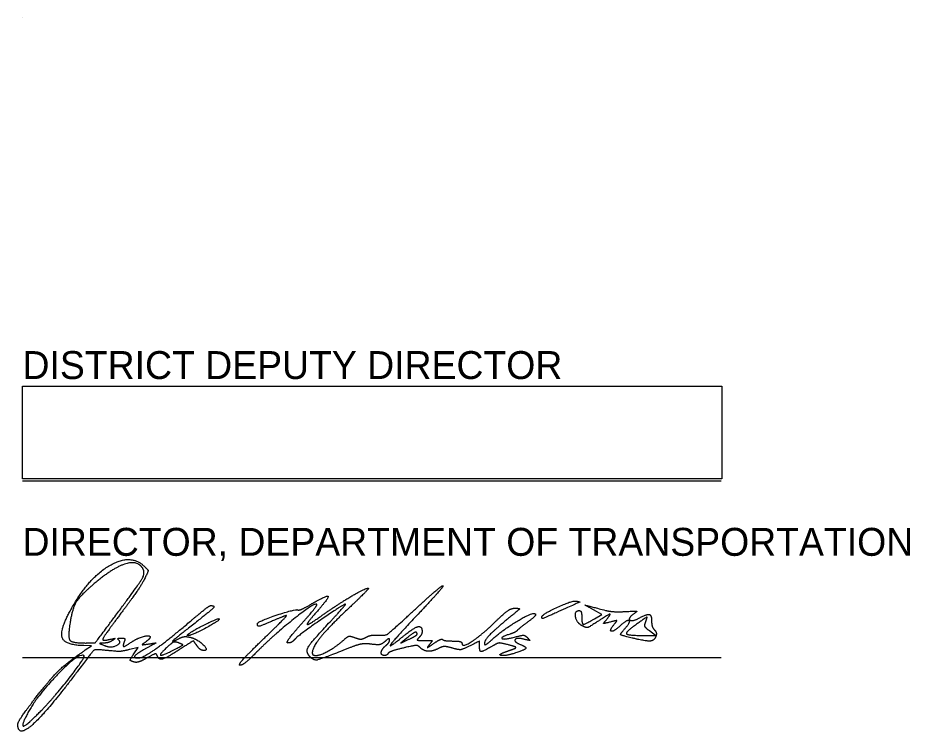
# Model space of a CAD drawing. Extents: x 0 to 91.3, y -0.7 to 22.
# Drawn here: x 24.504 to 28.975, y 7.3 to 10.875 of the extents above; entities that cross this region are included whole.
import ezdxf

# ---------------------------------------------------------------- set-up
doc = ezdxf.new("R2010")
doc.units = 0
doc.layers.add('SH_Data', color=7, linetype='Continuous')
doc.layers.add('SH_Text', color=7, linetype='Continuous')

msp = doc.modelspace()

# ---------------------------------------------------------------- linework, layer by layer
at = {"layer": 'SH_Data'}
for p, q in [((24.5279, 10.875), (24.5279, 10.875)), ((24.5279, 8.555), (28.0279, 8.555)), ((24.5279, 7.6691), (28.0279, 7.6691))]:
    msp.add_line(p, q, dxfattribs=at)
msp.add_lwpolyline([(24.5279, 8.565), (24.5279, 9.0299), (28.032, 9.0299), (28.032, 8.565)], close=True, dxfattribs=at)
at = {"layer": 'SH_Text'}
for p, q in [((24.9902, 7.8741), (24.9902, 7.8741)), ((27.1295, 7.8733), (27.1295, 7.8733)), ((25.3555, 7.7842), (25.3555, 7.7842)), ((26.5045, 7.7863), (26.5045, 7.7863)), ((25.3107, 7.7426), (25.3107, 7.7426)), ((25.7273, 7.7552), (25.7273, 7.7552)), ((27.582, 7.767), (27.582, 7.767))]:
    msp.add_line(p, q, dxfattribs=at)
for points in [[(27.3933, 7.8637), (27.4297, 7.8852), (27.3889, 7.9081)], [(27.642, 7.7802), (27.6982, 7.7802), (27.6695, 7.8024)], [(26.4527, 7.7666), (26.4232, 7.741), (26.4638, 7.7606)], [(24.8425, 7.7072), (24.8732, 7.7284), (24.8354, 7.729)], [(25.0855, 7.6873), (25.1067, 7.7197), (25.0649, 7.7096)]]:
    msp.add_lwpolyline(points, dxfattribs=at)
for points in [[(24.7789, 7.9249), (24.8651, 8.0752), (25.0732, 8.1913), (25.1389, 8.1256)], [(25.1299, 8.1164), (25.104, 8.1584), (24.9779, 8.1173), (24.8825, 8.0357)], [(24.9902, 7.8741), (25.1115, 8.0376), (25.144, 8.0938), (25.1299, 8.1164)], [(25.1389, 8.1256), (25.1577, 8.1068), (25.1577, 8.1018), (25.1394, 8.0634)], [(25.1394, 8.0634), (25.1284, 8.0404), (25.0767, 7.9648), (25.0245, 7.8955)], [(24.8825, 8.0357), (24.8159, 7.9786), (24.7771, 7.9145), (24.766, 7.8433)], [(26.0326, 7.8833), (26.1131, 7.9399), (26.2445, 8.0172), (26.2602, 8.0172)], [(26.2602, 8.0172), (26.265, 8.0172), (26.2237, 7.9746), (26.1684, 7.9225)], [(26.4869, 7.9037), (26.5619, 7.9728), (26.6279, 8.0295), (26.6336, 8.0295)], [(26.6336, 8.0295), (26.6394, 8.0296), (26.5873, 7.9695), (26.518, 7.8959)], [(25.9736, 7.9368), (26.0524, 7.983), (26.0646, 7.9698), (26.0054, 7.9025)], [(24.8354, 7.729), (24.7375, 7.7307), (24.7141, 7.8119), (24.7789, 7.9249)], [(25.369, 7.8514), (25.4194, 7.8942), (25.4649, 7.9294), (25.4701, 7.9295)], [(25.4701, 7.9295), (25.495, 7.93), (25.4716, 7.9044), (25.3857, 7.8372)], [(26.0017, 7.9366), (25.9921, 7.9462), (25.7824, 7.7793), (25.7045, 7.7)], [(26.142, 7.9361), (26.0929, 7.9084), (25.9046, 7.7761), (25.8914, 7.7602)], [(25.908, 7.9076), (25.9136, 7.9058), (25.9431, 7.9189), (25.9736, 7.9368)], [(25.9239, 7.8362), (25.9702, 7.888), (26.0052, 7.9331), (26.0017, 7.9366)], [(26.1684, 7.9225), (26.0687, 7.8288), (25.9795, 7.7206), (25.9795, 7.6936)], [(26.0768, 7.8572), (26.123, 7.9065), (26.1523, 7.942), (26.142, 7.9361)], [(26.8951, 7.8475), (26.9403, 7.8913), (26.9774, 7.917), (26.9951, 7.9166)], [(26.9951, 7.9166), (27.0194, 7.9161), (27.0156, 7.9098), (26.967, 7.8698)], [(27.1295, 7.8733), (27.1295, 7.8857), (27.2823, 7.956), (27.3012, 7.9523)], [(27.3012, 7.9523), (27.3219, 7.9482), (27.3226, 7.9487), (27.201, 7.894)], [(27.3889, 7.9081), (27.3461, 7.9323), (27.3452, 7.9323), (27.4482, 7.9059)], [(24.844, 7.7422), (24.8907, 7.7422), (24.8953, 7.7463), (24.9902, 7.8741)], [(25.0245, 7.8955), (24.9722, 7.8261), (24.9295, 7.7654), (24.9295, 7.7607)], [(25.7047, 7.8391), (25.7049, 7.8496), (25.8923, 7.9128), (25.908, 7.9076)], [(25.7273, 7.7552), (25.7983, 7.8237), (25.8537, 7.8797), (25.8502, 7.8797)], [(25.8502, 7.8797), (25.8468, 7.8797), (25.8178, 7.8684), (25.7857, 7.8547)], [(26.0054, 7.9025), (25.9774, 7.8706), (25.9545, 7.841), (25.9545, 7.8365)], [(25.9545, 7.8365), (25.9545, 7.8321), (25.9896, 7.8531), (26.0326, 7.8833)], [(26.3119, 7.7814), (26.3453, 7.7786), (26.3688, 7.795), (26.4869, 7.9037)], [(26.518, 7.8959), (26.3885, 7.7583), (26.3564, 7.711), (26.4386, 7.7788)], [(26.967, 7.8698), (26.8929, 7.8088), (26.842, 7.7553), (26.842, 7.7385)], [(26.8763, 7.7563), (26.93, 7.8051), (27.0769, 7.8951), (27.0938, 7.8895)], [(27.0938, 7.8895), (27.1022, 7.8867), (27.087, 7.868), (27.0599, 7.8478)], [(27.201, 7.894), (27.1385, 7.8659), (27.1295, 7.8633), (27.1295, 7.8733)], [(27.3305, 7.8291), (27.304, 7.8433), (27.293, 7.9047), (27.317, 7.9047)], [(27.317, 7.9047), (27.3238, 7.9047), (27.3295, 7.8906), (27.3295, 7.8734)], [(27.3295, 7.8734), (27.3295, 7.8366), (27.3438, 7.8344), (27.3933, 7.8637)], [(27.4529, 7.8589), (27.4773, 7.8885), (27.4615, 7.8847), (27.4052, 7.8475)], [(27.4482, 7.9059), (27.4688, 7.9006), (27.5138, 7.8979), (27.5482, 7.8998)], [(27.5482, 7.8998), (27.6031, 7.9029), (27.608, 7.9012), (27.5881, 7.8864)], [(27.5881, 7.8864), (27.5593, 7.865), (27.5822, 7.8486), (27.6159, 7.8666)], [(27.6497, 7.8479), (27.6596, 7.8737), (27.6514, 7.8706), (27.5888, 7.825)], [(27.6159, 7.8666), (27.6561, 7.8881), (27.6795, 7.8824), (27.6795, 7.8509)], [(24.766, 7.8433), (24.7545, 7.7699), (24.776, 7.7422), (24.844, 7.7422)], [(25.1076, 7.6672), (25.1307, 7.6672), (25.2567, 7.756), (25.369, 7.8514)], [(25.3857, 7.8372), (25.2925, 7.7642), (25.271, 7.7426), (25.315, 7.7661)], [(25.3555, 7.7842), (25.3759, 7.8021), (25.5079, 7.8679), (25.5131, 7.8627)], [(25.5131, 7.8627), (25.5193, 7.8566), (25.3767, 7.7797), (25.359, 7.7797)], [(25.7857, 7.8547), (25.7231, 7.8279), (25.7044, 7.8242), (25.7047, 7.8391)], [(25.8581, 7.7422), (25.8478, 7.7422), (25.8767, 7.7835), (25.9239, 7.8362)], [(25.9697, 7.6716), (25.9445, 7.6968), (25.9734, 7.7469), (26.0768, 7.8572)], [(26.4386, 7.7788), (26.487, 7.8187), (26.5295, 7.829), (26.5295, 7.8009)], [(26.7295, 7.7407), (26.7295, 7.7179), (26.8248, 7.7793), (26.8951, 7.8475)], [(27.0599, 7.8478), (27.0328, 7.8276), (27.0079, 7.8076), (27.0045, 7.8033)], [(27.4052, 7.8475), (27.3652, 7.8209), (27.3519, 7.8177), (27.3305, 7.8291)], [(27.4723, 7.8472), (27.4392, 7.8389), (27.4374, 7.84), (27.4529, 7.8589)], [(27.4924, 7.8364), (27.507, 7.854), (27.5047, 7.8552), (27.4723, 7.8472)], [(27.5211, 7.8277), (27.4892, 7.7977), (27.4661, 7.8047), (27.4924, 7.8364)], [(27.5462, 7.815), (27.5767, 7.8487), (27.5551, 7.8596), (27.5211, 7.8277)], [(27.5888, 7.825), (27.5461, 7.7939), (27.5626, 7.78), (27.642, 7.7802)], [(27.6695, 7.8024), (27.6491, 7.818), (27.6434, 7.8313), (27.6497, 7.8479)], [(27.6795, 7.8509), (27.6795, 7.8351), (27.6858, 7.8158), (27.6936, 7.808)], [(25.0736, 7.7466), (25.1025, 7.7664), (25.167, 7.7839), (25.167, 7.7719)], [(25.359, 7.7797), (25.3542, 7.7797), (25.3526, 7.7817), (25.3555, 7.7842)], [(26.2489, 7.7709), (26.2623, 7.7785), (26.2906, 7.7832), (26.3119, 7.7814)], [(26.5045, 7.7863), (26.5045, 7.7997), (26.4804, 7.7906), (26.4527, 7.7666)], [(26.4638, 7.7606), (26.4862, 7.7715), (26.5045, 7.783), (26.5045, 7.7863)], [(26.5295, 7.8009), (26.5295, 7.792), (26.5227, 7.7779), (26.5145, 7.7697)], [(26.9701, 7.7868), (26.9206, 7.7713), (26.9401, 7.7577), (26.9919, 7.7715)], [(27.0045, 7.8033), (27.001, 7.7991), (26.9856, 7.7916), (26.9701, 7.7868)], [(26.9919, 7.7715), (27.0302, 7.7817), (27.0455, 7.7811), (27.0575, 7.7689)], [(27.582, 7.767), (27.5272, 7.78), (27.5215, 7.7877), (27.5462, 7.815)], [(27.6936, 7.808), (27.7014, 7.8002), (27.7044, 7.7851), (27.7003, 7.7743)], [(24.9357, 7.7416), (24.9133, 7.7407), (24.9138, 7.7394), (24.9399, 7.7289)], [(24.9295, 7.7607), (24.9295, 7.7559), (24.9449, 7.7556), (24.9638, 7.76)], [(24.9795, 7.7553), (24.9692, 7.7483), (24.9495, 7.7421), (24.9357, 7.7416)], [(24.9399, 7.7289), (24.9698, 7.7169), (25.026, 7.7415), (25.0086, 7.7589)], [(24.9638, 7.76), (24.9894, 7.7659), (24.9934, 7.7647), (24.9795, 7.7553)], [(25.0086, 7.7589), (25.004, 7.7635), (25.0103, 7.7672), (25.0225, 7.7672)], [(25.0225, 7.7672), (25.037, 7.7672), (25.0422, 7.7608), (25.0375, 7.7484)], [(25.0375, 7.7484), (25.0285, 7.7252), (25.0414, 7.7245), (25.0736, 7.7466)], [(25.1453, 7.7479), (25.1264, 7.7341), (25.1284, 7.7328), (25.161, 7.7377)], [(25.167, 7.7719), (25.167, 7.7674), (25.1572, 7.7566), (25.1453, 7.7479)], [(25.161, 7.7377), (25.1977, 7.7432), (25.1976, 7.743), (25.1522, 7.7179)], [(25.3107, 7.7426), (25.2935, 7.7489), (25.277, 7.7438), (25.2576, 7.7261)], [(25.2826, 7.7063), (25.329, 7.73), (25.3325, 7.7346), (25.3107, 7.7426)], [(25.315, 7.7661), (25.3276, 7.7729), (25.3515, 7.775), (25.3681, 7.7708)], [(25.4011, 7.7294), (25.3843, 7.7534), (25.3822, 7.753), (25.3165, 7.7106)], [(25.3681, 7.7708), (25.4042, 7.7616), (25.4625, 7.7047), (25.4358, 7.7047)], [(25.617, 7.6304), (25.6067, 7.6306), (25.6563, 7.6868), (25.7273, 7.7552)], [(25.8914, 7.7602), (25.8831, 7.7503), (25.8682, 7.7422), (25.8581, 7.7422)], [(25.9975, 7.6797), (26.0192, 7.6797), (26.1006, 7.7249), (26.137, 7.7572)], [(26.137, 7.7572), (26.1573, 7.7752), (26.1701, 7.7779), (26.1939, 7.7688)], [(26.2749, 7.7362), (26.2457, 7.74), (26.2058, 7.7335), (26.1693, 7.7191)], [(26.1939, 7.7688), (26.2141, 7.7612), (26.2329, 7.7619), (26.2489, 7.7709)], [(26.3444, 7.7506), (26.3287, 7.7365), (26.3075, 7.732), (26.2749, 7.7362)], [(26.367, 7.7582), (26.367, 7.7653), (26.3568, 7.7619), (26.3444, 7.7506)], [(26.3482, 7.7297), (26.3585, 7.7382), (26.367, 7.7511), (26.367, 7.7582)], [(26.5145, 7.7697), (26.5028, 7.758), (26.5087, 7.7547), (26.541, 7.7547)], [(26.541, 7.7547), (26.5785, 7.7547), (26.5809, 7.7526), (26.5654, 7.7333)], [(26.5654, 7.7333), (26.5533, 7.7183), (26.5598, 7.7201), (26.5871, 7.7392)], [(26.5871, 7.7392), (26.6085, 7.7542), (26.6293, 7.7632), (26.6332, 7.7593)], [(26.6332, 7.7593), (26.6371, 7.7554), (26.6604, 7.7522), (26.6849, 7.7522)], [(26.6849, 7.7522), (26.7094, 7.7522), (26.7295, 7.747), (26.7295, 7.7407)], [(26.817, 7.7281), (26.817, 7.751), (26.8159, 7.751), (26.7698, 7.7282)], [(26.842, 7.7385), (26.842, 7.7311), (26.8574, 7.7391), (26.8763, 7.7563)], [(26.9621, 7.7331), (26.9233, 7.743), (26.9065, 7.7414), (26.8789, 7.7251)], [(27.0388, 7.7614), (27.0021, 7.7705), (26.9889, 7.7474), (27.0232, 7.7342)], [(27.0232, 7.7342), (27.0538, 7.7225), (27.0449, 7.7076), (26.9981, 7.6922)], [(27.0575, 7.7689), (27.0702, 7.756), (27.0666, 7.7545), (27.0388, 7.7614)], [(27.7003, 7.7743), (27.6922, 7.7532), (27.651, 7.7507), (27.582, 7.767)], [(24.5916, 7.465), (24.6692, 7.5654), (24.7493, 7.6427), (24.8425, 7.7072)], [(24.9237, 7.7073), (24.8903, 7.7106), (24.8786, 7.7001), (24.8019, 7.5984)], [(25.0649, 7.7096), (25.0246, 7.6998), (25.0023, 7.6995), (24.9237, 7.7073)], [(25.1522, 7.7179), (25.1011, 7.6897), (25.0814, 7.6672), (25.1076, 7.6672)], [(25.3165, 7.7106), (25.2476, 7.6662), (25.2101, 7.6565), (25.202, 7.6809)], [(25.2576, 7.7261), (25.2133, 7.6856), (25.2246, 7.6767), (25.2826, 7.7063)], [(25.4358, 7.7047), (25.4262, 7.7047), (25.4106, 7.7158), (25.4011, 7.7294)], [(25.7045, 7.7), (25.6667, 7.6615), (25.6273, 7.6302), (25.617, 7.6304)], [(26.1693, 7.7191), (26.0233, 7.6614), (25.9882, 7.6531), (25.9697, 7.6716)], [(25.9795, 7.6936), (25.9795, 7.686), (25.9876, 7.6797), (25.9975, 7.6797)], [(26.3412, 7.6797), (26.3229, 7.6797), (26.3274, 7.7124), (26.3482, 7.7297)], [(26.3594, 7.6901), (26.3559, 7.6844), (26.3477, 7.6797), (26.3412, 7.6797)], [(26.4355, 7.7171), (26.3972, 7.7079), (26.3629, 7.6958), (26.3594, 7.6901)], [(26.5199, 7.7193), (26.5088, 7.7304), (26.4887, 7.7299), (26.4355, 7.7171)], [(26.6162, 7.7168), (26.5854, 7.7003), (26.5376, 7.7016), (26.5199, 7.7193)], [(26.6807, 7.7168), (26.6538, 7.7246), (26.6307, 7.7245), (26.6162, 7.7168)], [(26.7698, 7.7282), (26.7324, 7.7097), (26.7138, 7.7073), (26.6807, 7.7168)], [(26.8789, 7.7251), (26.8339, 7.6985), (26.817, 7.6993), (26.817, 7.7281)], [(26.9981, 7.6922), (26.9515, 7.6768), (26.9042, 7.6825), (26.9482, 7.6982)], [(26.9482, 7.6982), (26.962, 7.7031), (26.9817, 7.7102), (26.992, 7.7139)], [(26.992, 7.7139), (27.0034, 7.7181), (26.9917, 7.7256), (26.9621, 7.7331)], [(24.8354, 7.6779), (24.8145, 7.6988), (24.596, 7.4732), (24.5497, 7.3828)], [(24.6198, 7.4016), (24.6874, 7.4706), (24.8431, 7.6702), (24.8354, 7.6779)], [(25.0843, 7.6473), (25.0661, 7.6542), (25.0662, 7.6579), (25.0855, 7.6873)], [(25.1508, 7.6671), (25.1252, 7.652), (25.0953, 7.643), (25.0843, 7.6473)], [(25.202, 7.6809), (25.1991, 7.6894), (25.1799, 7.6842), (25.1508, 7.6671)], [(24.8019, 7.5984), (24.6496, 7.3964), (24.5045, 7.2677), (24.5045, 7.3347)], [(24.5045, 7.3347), (24.5045, 7.3443), (24.5437, 7.403), (24.5916, 7.465)], [(24.5497, 7.3828), (24.5184, 7.3219), (24.55, 7.3303), (24.6198, 7.4016)]]:
    msp.add_open_spline(points, degree=2, dxfattribs=at)

# ---------------------------------------------------------------- texts
for s, p in [('DISTRICT DEPUTY DIRECTOR', (24.5279, 9.065)), ('DIRECTOR, DEPARTMENT OF TRANSPORTATION', (24.5279, 8.1791))]:
    msp.add_text(s, height=0.14, dxfattribs=at).set_placement(p)

doc.saveas('drawing.dxf')
